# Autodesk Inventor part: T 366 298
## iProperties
Company: Mayer & Müller AG Schaltgeräte
Created: 2006-03
Part Number: T 366 298
Material: 1.0308
Document SubType Name: Modeling
Designer: I.Baliuc
Description: Distanzbuchse
Density: 7.84 g/cm^3
HalbzeugNorm: DIN 2391
Zweck: Kontaktträger DC-Schalter
Abmessung: Rohr 14x2-(91,5)
Author: T.Messerschmitt
Keywords: 381014
Revision Number: 366298
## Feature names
1. Drehung1 [Revolution]
